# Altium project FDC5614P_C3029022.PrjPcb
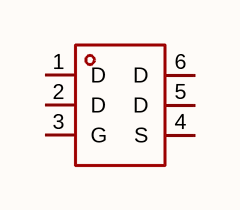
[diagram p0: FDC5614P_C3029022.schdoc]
1 sheet, 1 parts. Net scope: global (net labels, ports and power ports of the same name join across sheets).

## Sheet FDC5614P_C3029022.schdoc
size 127 x 101 mm

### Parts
Q?  fdc5614p_c3029022  [SOT-23-6_L2.9-W1.6-P0.95-LS2.8-BR]  (value not drawn)

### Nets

Not connected (* = marked no-connect by the designer): Q? 1(D) 2(D) 3(G) 4(S) 5(D) 6(D)

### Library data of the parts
Q? = fdc5614p_c3029022: 数量:1个P沟道;漏源电压(Vdss):60V;连续漏极电流(Id):3.3A;导通电阻(RDS(on)):80mΩ@10V;耗散功率(Pd):2W;阈值电压(Vgs(th)):1.6V;; Manufacturer: MSKSEMI(美森科); AddInBom: yes; ModelId: 18da8f6c14a34920b3e136b5c401a119; ModelName: SOT-23-6_L2.9-W1.6-H1.5-LS2.8-P0.95; ModelTransform: 110.73671,114.173,0,180,0,0,0.001,-0.003,0; Number: 1个P沟道; Drain to Source Voltage: 60V; Current - Continuous Drain(Id): 3.3A; Pd - Power Dissipation: 2W; Gate Threshold Voltage (Vgs(th)): 1.6V; Gate Charge(Qg): 10nC@10V; Input Capacitance(Ciss): 720pF; Reverse Transfer Capacitance (Crss@Vds): 32pF; Output Capacitance(Coss): 42pF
